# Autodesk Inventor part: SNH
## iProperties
Author: Administrator
Shininess: 41.0
PropertySet Name: _Private Model Information
Length Units: 11269
Angle Units: 11283
Time Units: 11279
Mass Units: 11290
Length Display Precision: 3
Angle Display Precision: 2
Compacted: True
Created: 2001-07
Part Number: SNH
Document SubType Name: Modellazione
Designer: Administrator
Control State: 0
Master: False
Checked Out: False
PropertySet Name: Design Tracking Control
Density: 1.0
Volumn: 1327.0016086968312
Area: 1822.1231962515228
PropertySet Name: Model Information
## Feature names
1. Estrusione1 [Extrusion]
2. Estrusione2 [Extrusion]
3. Specchio1 [Mirror]
4. Estrusione3 [Extrusion]
5. Foro1 [Hole]
6. Smusso1 [Chamfer]
7. Loft3
8. Loft4
9. Specchio4 [Mirror]
10. Specchio5 [Mirror]
11. Rivoluzione1 [Revolution]
12. Rivoluzione2 [Revolution]
13. Specchio6 [Mirror]
14. Raccordo5 [Fillet]
